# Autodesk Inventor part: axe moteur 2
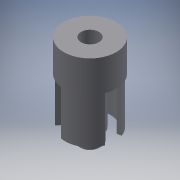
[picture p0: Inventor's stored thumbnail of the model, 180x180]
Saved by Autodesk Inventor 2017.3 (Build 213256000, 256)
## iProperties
Part Number: axe moteur 2
Material: Générique
Document SubType Name: Modeling
Designer: ficho
Density: 1 g/cm^3
Appearance: Par défaut
Author: ficho
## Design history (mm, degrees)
sketch "Esquisse1"
  geometry: C1 r 5 at (-5, 0) reference; C2 r 4.5 at (-5, 0); C3 r 3.25 at (-5, 0); 1 further point
  constraints: 2 centre point
  dimensions: "d0" = 0.5 radial gap between concentric circles of C1 C2; "d2" = 6.5 diameter of C3
  node "Référence1"
node "Plan de construction1"
extrude "Extrusion1" new body sketch "Esquisse1" stored distance "d3" = 10; taper "d4" = 0 deg
sketch "Esquisse2"
  geometry: C1 r 3.25 at (0, 0) reference; C2 r 4.5 at (0, 0) reference; 1 further point
node "Plan de construction2"
extrude "Extrusion2" join sketch "Esquisse2" stored distance "d5" = 10; taper "d6" = 0 deg
sketch "Esquisse3"
  geometry: C1 r 4.5 at (0, 0) reference; C2 r 9.5 at (0, 0); 1 further point
  constraints: 1 centre point
  dimensions: "d7" = 5 radial gap between concentric circles of C1 C2
node "Plan de construction3"
extrude "Extrusion3" join sketch "Esquisse3" stored distance "d8" = 0; taper "d9" = 0 deg
sketch "Esquisse4"
  geometry: L1 (-8.478, 3.02)-(-6.982, 2.738); L2 (1.119, 7.416)-(1.623, 8.852); L3 (6.855, 5.832)-(5.863, 4.677); L4 (5.863, -4.677)-(6.855, -5.832); L5 (1.623, -8.852)-(1.119, -7.416); L6 (-6.982, -2.738)-(-8.478, -3.02); C1 r 4.5 at (0, 0); A1 r 7.5 centre (0, 0) between (1.119, 7.416) and (-6.982, 2.738); A2 r 9 centre (0, 0) between (1.623, 8.852) and (-8.478, 3.02); A3 r 7.5 centre (0, 0) between (5.863, -4.677) and (5.863, 4.677); A4 r 9 centre (0, 0) between (6.855, -5.832) and (6.855, 5.832); A5 r 7.5 centre (0, 0) between (-6.982, -2.738) and (1.119, -7.416); A6 r 9 centre (0, 0) between (-8.478, -3.02) and (1.623, -8.852); 1 further point
  constraints: 12 end point, 12 point on circle, 7 centre point
node "Plan de construction4"
extrude "Extrusion4" join sketch "Esquisse4" stored distance "d13" = 10; taper "d14" = 0 deg
sketch "Esquisse5"
  geometry: C1 r 4.5 at (0, 0) reference; 1 further point
extrude "Extrusion5" join sketch "Esquisse5" distance "d15" = 5; taper "d16" = 0 deg
sketch "Esquisse6"
  geometry: C1 r 5 at (0, 0) reference; C2 r 4 at (0, 0); 1 further point
  constraints: 1 centre point, 1 coincident
  dimensions: "d17" = 8 diameter of C2
extrude "Extrusion6" join sketch "Esquisse6" distance "d18" = 5; taper "d19" = 0 deg
chamfer "Chanfrein1" distance "d20" = 0.8; stored, may be unused: second distance "d21" = 2, angle "d22" = 45 deg
sketch "Esquisse7"
  geometry: L1 (5.863, 4.677)-(6.855, 5.832) reference; L2 (6.855, -5.832)-(5.863, -4.677) reference; L3 (1.119, -7.416)-(1.623, -8.852) reference; L4 (-8.478, -3.02)-(-6.982, -2.738) reference; L5 (1.623, 8.852)-(1.119, 7.416) reference; L6 (-6.982, 2.738)-(-8.478, 3.02) reference; C1 r 4.5 at (0, 0) reference; C2 r 9.5 at (0, 0) reference; A1 r 7.5 centre (0, 0) between (5.863, -4.677) and (5.863, 4.677) reference; A2 r 9 centre (0, 0) between (6.855, -5.832) and (6.855, 5.832) reference; A3 r 7.5 centre (0, 0) between (-6.982, -2.738) and (1.119, -7.416) reference; A4 r 9 centre (0, 0) between (-8.478, -3.02) and (1.623, -8.852) reference; A5 r 7.5 centre (0, 0) between (1.119, 7.416) and (-6.982, 2.738) reference; A6 r 9 centre (0, 0) between (1.623, 8.852) and (-8.478, 3.02) reference; 1 further point
extrude "Extrusion7" join sketch "Esquisse7" distance "d23" = 4; taper "d24" = 0 deg
sketch "Esquisse8"
  geometry: L1 (2.5, 2.077)-(2.5, 0); L2 (2.5, 0)-(2.5, -2.077); A1 r 3.25 centre (0, 0) between (2.5, -2.077) and (2.5, 2.077); 1 further point
  constraints: 4 end point, 2 point on circle, 1 centre point
extrude "Extrusion8" join sketch "Esquisse8" stored distance "d25" = 4; taper "d26" = 0 deg
sketch "Esquisse9"
  geometry: C1 r 3.25 at (0, 0); A1 r 3.25 centre (0, 0) between (2.5, 2.077) and (2.5, -2.077) reference
  constraints: 1 centre point, 1 coincident
extrude "Extrusion9" cut sketch "Esquisse9" distance "d27" = 4; taper "d28" = 0 deg
node "Solide1"
node "Référence12"
node "Boucle projetée1"
